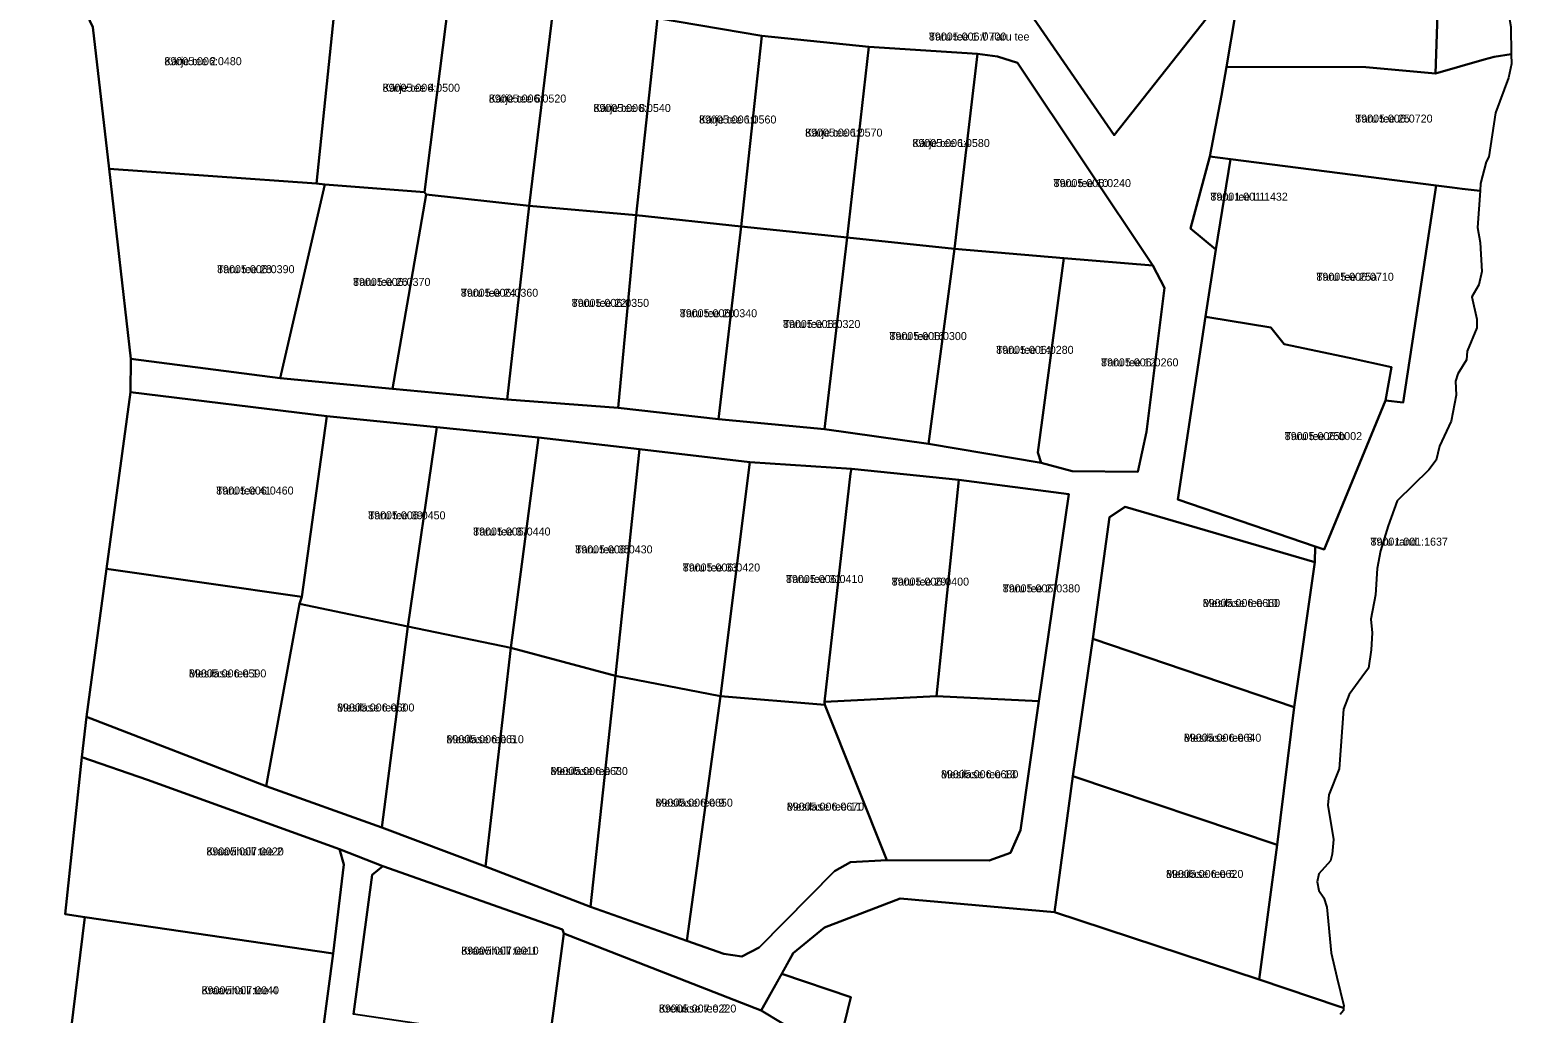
# Model space of a CAD drawing. Extents: x 526849 to 562296, y 6591741 to 6618546.
# Drawn here: x 551338.6 to 551616.5, y 6597308.8 to 6597493.2 of the extents above; entities that cross this region are included whole.
import ezdxf

# ---------------------------------------------------------------- set-up
doc = ezdxf.new("R2010")
doc.units = 0
for name, color, linetype in [('L_AADRESS', 7, 'Continuous'), ('PIIR', 7, 'Continuous'), ('TUNNUS', 7, 'Continuous')]:
    doc.layers.add(name, color=color, linetype=linetype)

msp = doc.modelspace()

# ---------------------------------------------------------------- linework, layer by layer
at = {"layer": 'PIIR'}
for points in [[(550642.16, 6598609.49), (550659.82, 6598605.14), (550668.05, 6598592.24), (550686.56, 6598557.97), (551117.21, 6597760.6), (551147.24, 6597726.55), (551257.76, 6597622.75), (551265.4, 6597615.62), (551270.73, 6597618.95), (551273.1, 6597610.57), (551301.36, 6597574.38), (551331.62, 6597533.44), (551350.49, 6597493.63), (551353.55, 6597467.1), (551357.58, 6597431.51), (551357.52, 6597425.22), (551353.03, 6597392.12), (551349.26, 6597364.37), (551348.43, 6597356.79), (551345.28, 6597327.37), (551348.98, 6597326.82), (551346.35, 6597305.43)], [(551524.95, 6597497.97), (551541.83, 6597473.44), (551565.74, 6597503.64)], [(551564.57, 6597496.23), (551562.88, 6597486.25), (551561.99, 6597480.84), (551559.76, 6597469.43), (551556.15, 6597455.94), (551560.92, 6597451.99), (551559, 6597439.39), (551553.77, 6597405.12), (551579.5, 6597396.33), (551579.43, 6597393.36), (551543.94, 6597403.71), (551540.99, 6597401.81), (551537.84, 6597379.02), (551534.11, 6597353.23), (551530.68, 6597327.76), (551501.76, 6597330.34), (551487.59, 6597324.91), (551481.73, 6597320.05), (551475.69, 6597309.35), (551438.73, 6597323.73), (551438.51, 6597324.53), (551404.84, 6597336.38), (551396.71, 6597339.57), (551360.7, 6597352.59), (551348.43, 6597356.79), (551349.26, 6597364.37), (551382.96, 6597351.4), (551404.64, 6597343.62), (551424.03, 6597336.29), (551443.73, 6597328.73), (551461.8, 6597322.36), (551468.73, 6597319.93), (551472.11, 6597319.45), (551475.35, 6597321.12), (551489.42, 6597335.42), (551492.43, 6597337.14), (551499.23, 6597337.49), (551518.44, 6597337.47), (551522.42, 6597338.85), (551524.33, 6597343.13), (551527.75, 6597367.33), (551533.37, 6597406.1), (551512.72, 6597408.83), (551492.64, 6597410.89), (551473.59, 6597412.13), (551452.88, 6597414.56), (551433.98, 6597416.71), (551414.91, 6597418.66), (551394.29, 6597420.73), (551357.52, 6597425.22), (551357.58, 6597431.51), (551385.55, 6597427.88), (551406.63, 6597425.86), (551428.13, 6597423.83), (551448.92, 6597422.32), (551467.74, 6597420.2), (551487.55, 6597418.3), (551507.06, 6597415.58), (551528.19, 6597411.99), (551533.97, 6597410.4), (551546.26, 6597410.29), (551547.9, 6597417.77), (551551.27, 6597444.77), (551549.08, 6597448.97), (551523.76, 6597486.95), (551520.01, 6597488.19), (551516.25, 6597488.66), (551495.9, 6597489.98), (551475.86, 6597492.06), (551456.31, 6597495.37)], [(551392.56, 6597297.89), (551395.52, 6597319.99), (551397.5, 6597336.71), (551396.71, 6597339.57), (551404.84, 6597336.38), (551402.81, 6597334.73), (551399.34, 6597308.65)], [(551486.41, 6597286.7), (551492.52, 6597311.82), (551479.56, 6597316.2), (551481.73, 6597320.05), (551487.59, 6597324.91), (551501.76, 6597330.34), (551530.68, 6597327.76), (551569.03, 6597315.11), (551584.02, 6597310.08), (551584.84, 6597309.81), (551584.8, 6597309.29), (551584.21, 6597308.56)]]:
    msp.add_lwpolyline(points, dxfattribs=at)
for points in [[(551602.24, 6597556.83), (551616.06, 6597556.12), (551616.16, 6597556.12), (551615.91, 6597552.24), (551615.29, 6597547.89), (551615.23, 6597544.17), (551616.35, 6597532.64), (551615.52, 6597529.55), (551616.47, 6597517.33), (551615.66, 6597511.77), (551615.31, 6597502.38), (551615.34, 6597498.71), (551616.16, 6597493.75), (551616.27, 6597488.59), (551613.07, 6597488.1), (551611.21, 6597487.58), (551602.04, 6597485), (551602.5, 6597497.88)], [(551350.49, 6597493.63), (551331.62, 6597533.44), (551342.79, 6597538.24), (551346.69, 6597534.7), (551355.94, 6597510.14), (551374.5, 6597502.05), (551396.12, 6597500.57), (551392.38, 6597464.36), (551353.55, 6597467.1)], [(551524.95, 6597497.97), (551570.61, 6597513.92), (551570.54, 6597510.69), (551569.12, 6597507.13), (551565.74, 6597503.64), (551541.83, 6597473.44)], [(551586.96, 6597509.8), (551587.8, 6597499.23), (551602.5, 6597497.88), (551602.04, 6597485), (551588.99, 6597486.15), (551562.88, 6597486.25), (551564.57, 6597496.23), (551565.74, 6597503.64), (551569.12, 6597507.13), (551570.54, 6597510.69)], [(551392.38, 6597464.36), (551396.12, 6597500.57), (551417.15, 6597498.69), (551412.63, 6597462.71), (551393.97, 6597464.14)], [(551412.63, 6597462.71), (551417.15, 6597498.69), (551436.72, 6597497.03), (551432.22, 6597460.17), (551412.91, 6597462.32)], [(551436.72, 6597497.03), (551456.31, 6597495.37), (551452.26, 6597458.44), (551432.22, 6597460.17)], [(551456.31, 6597495.37), (551475.86, 6597492.06), (551471.98, 6597456.26), (551452.26, 6597458.44)], [(551475.86, 6597492.06), (551495.9, 6597489.98), (551491.83, 6597454.25), (551471.98, 6597456.26)], [(551495.9, 6597489.98), (551516.25, 6597488.66), (551511.93, 6597452.08), (551491.83, 6597454.25)], [(551516.25, 6597488.66), (551520.01, 6597488.19), (551523.76, 6597486.95), (551549.08, 6597448.97), (551532.44, 6597450.36), (551511.93, 6597452.08)], [(551561.99, 6597480.84), (551562.88, 6597486.25), (551588.99, 6597486.15), (551602.04, 6597485), (551611.21, 6597487.58), (551613.07, 6597488.1), (551616.27, 6597488.59), (551616.31, 6597486.77), (551615.76, 6597484.15), (551613.32, 6597477.58), (551612.06, 6597469.35), (551611.55, 6597468.43), (551610.52, 6597464.38), (551610.42, 6597462.95), (551607.04, 6597463.36), (551605.17, 6597463.6), (551602.22, 6597463.98), (551563.63, 6597468.93), (551559.76, 6597469.43)], [(551560.92, 6597451.99), (551556.15, 6597455.94), (551559.76, 6597469.43), (551563.63, 6597468.93)], [(551563.63, 6597468.93), (551602.22, 6597463.98), (551595.98, 6597423.32), (551592.69, 6597423.7), (551593.84, 6597429.92), (551585.92, 6597431.65), (551573.7, 6597434.24), (551571.2, 6597437.38), (551559.42, 6597439.32), (551559, 6597439.39), (551560.92, 6597451.99)], [(551353.55, 6597467.1), (551392.38, 6597464.36), (551393.97, 6597464.14), (551385.55, 6597427.88), (551357.58, 6597431.51)], [(551393.97, 6597464.14), (551412.63, 6597462.71), (551412.91, 6597462.32), (551406.63, 6597425.86), (551385.55, 6597427.88)], [(551610.42, 6597462.95), (551609.96, 6597456.13), (551610.44, 6597453.27), (551610.76, 6597447.87), (551610.2, 6597445.34), (551608.85, 6597443.11), (551609.8, 6597438.91), (551609.81, 6597437.27), (551608.01, 6597432.92), (551607.9, 6597431.29), (551606.23, 6597428.67), (551605.84, 6597427.32), (551605.92, 6597424.67), (551605.02, 6597419.78), (551602.82, 6597415.09), (551602.19, 6597412.47), (551600.84, 6597410.65), (551594.88, 6597404.85), (551593.22, 6597400.17), (551591.79, 6597395.49), (551591.15, 6597392.15), (551590.83, 6597387.24), (551589.96, 6597382.71), (551590.2, 6597380.09), (551590.04, 6597376.91), (551589.49, 6597373.5), (551588.29, 6597371.8), (551585.91, 6597368.57), (551584.85, 6597365.82), (551584.01, 6597354.61), (551582.1, 6597349.74), (551581.89, 6597347.83), (551582.95, 6597341.38), (551582.73, 6597338.62), (551582.42, 6597337.35), (551580.19, 6597334.92), (551579.88, 6597333.44), (551580.21, 6597331.84), (551581.14, 6597330.47), (551581.68, 6597328.68), (551582.52, 6597320.1), (551583.6, 6597315.6), (551584.87, 6597310.21), (551584.84, 6597309.81), (551584.02, 6597310.08), (551569.03, 6597315.11), (551572.43, 6597340.38), (551575.58, 6597366.21), (551579.43, 6597393.36), (551579.5, 6597396.33), (551581.19, 6597395.72), (551592.69, 6597423.7), (551595.98, 6597423.32), (551602.22, 6597463.98), (551605.17, 6597463.6), (551607.04, 6597463.36)], [(551412.91, 6597462.32), (551432.22, 6597460.17), (551428.13, 6597423.83), (551406.63, 6597425.86)], [(551432.22, 6597460.17), (551452.26, 6597458.44), (551448.92, 6597422.32), (551428.13, 6597423.83)], [(551452.26, 6597458.44), (551471.98, 6597456.26), (551467.74, 6597420.2), (551448.92, 6597422.32)], [(551471.98, 6597456.26), (551491.83, 6597454.25), (551487.55, 6597418.3), (551467.74, 6597420.2)], [(551491.83, 6597454.25), (551511.93, 6597452.08), (551507.06, 6597415.58), (551487.55, 6597418.3)], [(551511.93, 6597452.08), (551532.44, 6597450.36), (551527.53, 6597413.91), (551528.19, 6597411.99), (551507.06, 6597415.58)], [(551528.19, 6597411.99), (551527.53, 6597413.91), (551532.44, 6597450.36), (551549.08, 6597448.97), (551551.27, 6597444.77), (551547.9, 6597417.77), (551546.26, 6597410.29), (551533.97, 6597410.4)], [(551559, 6597439.39), (551559.42, 6597439.32), (551571.2, 6597437.38), (551573.7, 6597434.24), (551585.92, 6597431.65), (551593.84, 6597429.92), (551592.69, 6597423.7), (551581.19, 6597395.72), (551579.5, 6597396.33), (551553.77, 6597405.12)], [(551357.52, 6597425.22), (551394.29, 6597420.73), (551389.61, 6597386.85), (551353.03, 6597392.12)], [(551389.61, 6597386.85), (551394.29, 6597420.73), (551414.91, 6597418.66), (551409.49, 6597381.29), (551389.22, 6597385.57)], [(551414.91, 6597418.66), (551433.98, 6597416.71), (551428.83, 6597377.28), (551409.49, 6597381.29)], [(551433.98, 6597416.71), (551452.88, 6597414.56), (551448.43, 6597372.08), (551428.83, 6597377.28)], [(551452.88, 6597414.56), (551473.59, 6597412.13), (551468.08, 6597368.27), (551448.43, 6597372.08)], [(551473.59, 6597412.13), (551492.64, 6597410.89), (551492.46, 6597410.01), (551487.59, 6597367.2), (551487.62, 6597366.61), (551468.08, 6597368.27)], [(551492.46, 6597410.01), (551492.64, 6597410.89), (551512.72, 6597408.83), (551508.58, 6597368.25), (551487.59, 6597367.2)], [(551512.72, 6597408.83), (551533.37, 6597406.1), (551527.75, 6597367.33), (551508.58, 6597368.25)], [(551540.99, 6597401.81), (551543.94, 6597403.71), (551579.43, 6597393.36), (551575.58, 6597366.21), (551537.84, 6597379.02)], [(551353.03, 6597392.12), (551389.61, 6597386.85), (551389.22, 6597385.57), (551382.96, 6597351.4), (551349.26, 6597364.37)], [(551389.22, 6597385.57), (551409.49, 6597381.29), (551404.64, 6597343.62), (551382.96, 6597351.4)], [(551409.49, 6597381.29), (551428.83, 6597377.28), (551424.03, 6597336.29), (551404.64, 6597343.62)], [(551428.83, 6597377.28), (551448.43, 6597372.08), (551443.73, 6597328.73), (551424.03, 6597336.29)], [(551537.84, 6597379.02), (551575.58, 6597366.21), (551572.43, 6597340.38), (551534.11, 6597353.23)], [(551448.43, 6597372.08), (551468.08, 6597368.27), (551461.8, 6597322.36), (551443.73, 6597328.73)], [(551472.11, 6597319.45), (551468.73, 6597319.93), (551461.8, 6597322.36), (551468.08, 6597368.27), (551487.62, 6597366.61), (551499.23, 6597337.49), (551492.43, 6597337.14), (551489.42, 6597335.42), (551475.35, 6597321.12)], [(551487.62, 6597366.61), (551487.59, 6597367.2), (551508.58, 6597368.25), (551527.75, 6597367.33), (551524.33, 6597343.13), (551522.42, 6597338.85), (551518.44, 6597337.47), (551499.23, 6597337.49)], [(551345.28, 6597327.37), (551348.43, 6597356.79), (551360.7, 6597352.59), (551396.71, 6597339.57), (551397.5, 6597336.71), (551395.52, 6597319.99), (551348.98, 6597326.82)], [(551534.11, 6597353.23), (551572.43, 6597340.38), (551569.03, 6597315.11), (551530.68, 6597327.76)], [(551402.81, 6597334.73), (551404.84, 6597336.38), (551438.51, 6597324.53), (551438.73, 6597323.73), (551435.96, 6597303.19), (551399.34, 6597308.65)], [(551348.98, 6597326.82), (551395.52, 6597319.99), (551392.56, 6597297.89), (551346.35, 6597305.43)], [(551435.96, 6597303.19), (551438.73, 6597323.73), (551475.69, 6597309.35), (551479.63, 6597306.94), (551483.42, 6597304.52), (551483.68, 6597296.2), (551482.69, 6597294.15), (551435.4, 6597299.59)], [(551474.88, 6597267.34), (551470.43, 6597269.93), (551473.22, 6597275.2), (551482.69, 6597294.15), (551483.68, 6597296.2), (551483.42, 6597304.52), (551479.63, 6597306.94), (551475.69, 6597309.35), (551479.56, 6597316.2), (551492.52, 6597311.82), (551486.41, 6597286.7)]]:
    msp.add_lwpolyline(points, close=True, dxfattribs=at)

# ---------------------------------------------------------------- texts
at = {"layer": 'L_AADRESS'}
for s, p in [('Taru tee 1 // Taru tee', (551507.14, 6597491.15)), ('Kärje tee 2', (551363.87, 6597486.53)), ('Kärje tee 4', (551404.77, 6597481.55)), ('Kärje tee 6', (551424.68, 6597479.53)), ('Kärje tee 8', (551444.27, 6597477.76)), ('Kärje tee 10', (551464.06, 6597475.6)), ('Taru tee 25', (551587.02, 6597475.77)), ('Kärje tee 12', (551483.94, 6597473.14)), ('Kärje tee 14', (551504.04, 6597471.19)), ('Taru tee 10', (551530.5, 6597463.68)), ('Taru tee L1', (551559.89, 6597461.13)), ('Taru tee 28', (551373.76, 6597447.54)), ('Taru tee 26', (551399.23, 6597445.15)), ('Taru tee 25a', (551579.75, 6597446.12)), ('Taru tee 24', (551419.43, 6597443.12)), ('Taru tee 22', (551440.2, 6597441.22)), ('Taru tee 20', (551460.45, 6597439.28)), ('Taru tee 18', (551479.79, 6597437.26)), ('Taru tee 16', (551499.74, 6597435)), ('Taru tee 14', (551519.75, 6597432.42)), ('Taru tee 12', (551539.4, 6597430.07)), ('Taru tee 25b', (551573.81, 6597416.25)), ('Taru tee 41', (551373.59, 6597406.04)), ('Taru tee 39', (551402.06, 6597401.4)), ('Taru tee 37', (551421.73, 6597398.36)), ('Taru tee 35', (551440.86, 6597395.01)), ('Taru rand', (551589.89, 6597396.46)), ('Taru tee 33', (551461.01, 6597391.62)), ('Taru tee 31', (551480.36, 6597389.46)), ('Taru tee 29', (551500.16, 6597388.97)), ('Taru tee 27', (551520.97, 6597387.7)), ('Mesilase tee 10', (551558.45, 6597384.96)), ('Mesilase tee 1', (551368.48, 6597371.76)), ('Mesilase tee 3', (551396.23, 6597365.37)), ('Mesilase tee 5', (551416.73, 6597359.42)), ('Mesilase tee 8', (551554.92, 6597359.7)), ('Mesilase tee 7', (551436.23, 6597353.46)), ('Mesilase tee 13', (551509.4, 6597352.86)), ('Mesilase tee 9', (551455.9, 6597347.53)), ('Mesilase tee 11', (551480.51, 6597346.79)), ('Kraavihalli tee 2', (551371.75, 6597338.39)), ('Mesilase tee 6', (551551.57, 6597334.17)), ('Kraavihalli tee 1', (551419.51, 6597319.79)), ('Kraavihalli tee 4', (551370.85, 6597312.36)), ('Kreiukse tee 2', (551456.55, 6597308.94))]:
    msp.add_text(s, height=1.5, dxfattribs=at).set_placement(p)
at = {"layer": 'TUNNUS'}
for s, p in [('89005:006:0700', (551507.14, 6597491.15)), ('89005:006:0480', (551363.87, 6597486.53)), ('89005:006:0500', (551404.77, 6597481.55)), ('89005:006:0520', (551424.68, 6597479.53)), ('89005:006:0540', (551444.27, 6597477.76)), ('89005:006:0560', (551464.06, 6597475.6)), ('89005:006:0720', (551587.02, 6597475.77)), ('89005:006:0570', (551483.94, 6597473.14)), ('89005:006:0580', (551504.04, 6597471.19)), ('89005:006:0240', (551530.5, 6597463.68)), ('89001:001:1432', (551559.89, 6597461.13)), ('89005:006:0390', (551373.76, 6597447.54)), ('89005:006:0370', (551399.23, 6597445.15)), ('89005:006:0710', (551579.75, 6597446.12)), ('89005:006:0360', (551419.43, 6597443.12)), ('89005:006:0350', (551440.2, 6597441.22)), ('89005:006:0340', (551460.45, 6597439.28)), ('89005:006:0320', (551479.79, 6597437.26)), ('89005:006:0300', (551499.74, 6597435)), ('89005:006:0280', (551519.75, 6597432.42)), ('89005:006:0260', (551539.4, 6597430.07)), ('89005:006:0002', (551573.81, 6597416.25)), ('89005:006:0460', (551373.59, 6597406.04)), ('89005:006:0450', (551402.06, 6597401.4)), ('89005:006:0440', (551421.73, 6597398.36)), ('89005:006:0430', (551440.86, 6597395.01)), ('89001:001:1637', (551589.89, 6597396.46)), ('89005:006:0420', (551461.01, 6597391.62)), ('89005:006:0410', (551480.36, 6597389.46)), ('89005:006:0400', (551500.16, 6597388.97)), ('89005:006:0380', (551520.97, 6597387.7)), ('89005:006:0660', (551558.45, 6597384.96)), ('89005:006:0590', (551368.48, 6597371.76)), ('89005:006:0600', (551396.23, 6597365.37)), ('89005:006:0610', (551416.73, 6597359.42)), ('89005:006:0640', (551554.92, 6597359.7)), ('89005:006:0630', (551436.23, 6597353.46)), ('89005:006:0680', (551509.4, 6597352.86)), ('89005:006:0650', (551455.9, 6597347.53)), ('89005:006:0670', (551480.51, 6597346.79)), ('89005:007:0020', (551371.75, 6597338.39)), ('89005:006:0620', (551551.57, 6597334.17)), ('89005:007:0010', (551419.51, 6597319.79)), ('89005:007:0040', (551370.85, 6597312.36)), ('89005:007:0220', (551456.55, 6597308.94))]:
    msp.add_text(s, height=1.5, dxfattribs=at).set_placement(p)

doc.saveas('drawing.dxf')
